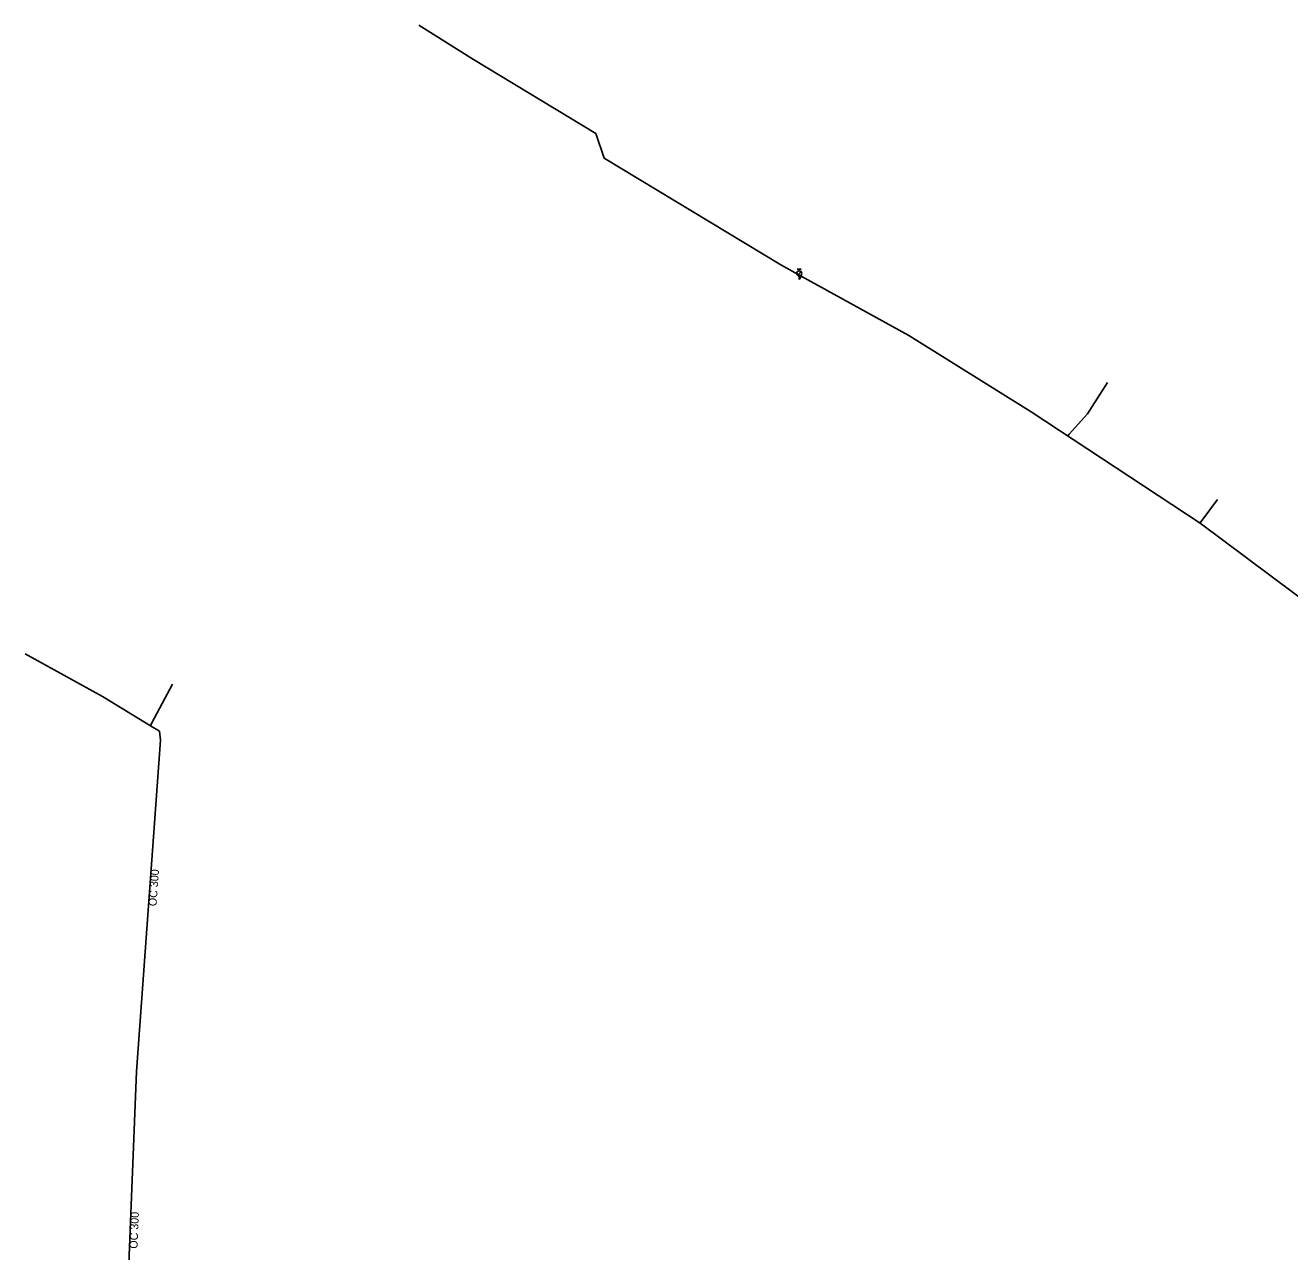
# Model space of a CAD drawing. Extents: x -513141 to -512601, y -1130827 to -1130115.
# Drawn here: x -513094.7 to -512940.6, y -1130264 to -1130114.6 of the extents above; entities that cross this region are included whole.
import ezdxf

# ---------------------------------------------------------------- set-up
doc = ezdxf.new("R2010")
doc.units = 0
for name, color, linetype in [('Default', 7, 'Continuous'), ('MoLevel 10', 7, 'Continuous'), ('MoLevel 12', 7, 'Continuous'), ('MoLevel 15', 7, 'Continuous'), ('MoLevel 32', 7, 'Continuous')]:
    doc.layers.add(name, color=color, linetype=linetype)

# ---------------------------------------------------------------- blocks, each defined once
blk = doc.blocks.new('0.05')
at = {"layer": 'Default'}
for p, q in [((-0.01, 0.05), (0.01, 0.05)), ((-0.009, 0.021), (0.009, 0.039)), ((0, 0.0425), (0, 0.05)), ((0, 0), (0, 0.0175))]:
    blk.add_line(p, q, dxfattribs=at)
blk.add_circle((0, 0.03), 0.0125, dxfattribs=at)

msp = doc.modelspace()

# ---------------------------------------------------------------- linework, layer by layer
at = {"layer": 'MoLevel 10'}
for p, q in [((-513040.02, -1130118.75), (-513046.69, -1130114.57)), ((-513025.13, -1130127.76), (-513040.02, -1130118.75)), ((-513024.13, -1130130.75), (-513025.13, -1130127.76)), ((-513002.59, -1130143.74), (-513024.13, -1130130.75)), ((-513000.09, -1130145.12), (-513002.59, -1130143.74)), ((-513000.18, -1130145.28), (-513000.34, -1130145.55)), ((-513000.09, -1130145.12), (-513000.18, -1130145.28)), ((-512986.97, -1130152.37), (-513000.09, -1130145.12)), ((-512972.06, -1130161.66), (-512986.97, -1130152.37)), ((-512951.49, -1130175.24), (-512972.06, -1130161.66)), ((-512931.11, -1130190.44), (-512951.49, -1130175.24)), ((-513094.66, -1130191.16), (-513085.27, -1130196.35)), ((-513079.22, -1130199.54), (-513076.71, -1130194.83)), ((-513085.27, -1130196.35), (-513085.06, -1130196.47)), ((-513085.06, -1130196.47), (-513079.42, -1130199.91)), ((-513079.42, -1130199.91), (-513079.22, -1130199.54)), ((-513079.42, -1130199.91), (-513078.31, -1130200.59)), ((-513078.31, -1130200.59), (-513078.19, -1130201.68)), ((-513078.19, -1130201.68), (-513081.11, -1130242.02)), ((-513081.11, -1130242.02), (-513082.81, -1130285.18))]:
    msp.add_line(p, q, dxfattribs=at)
at = {"layer": 'MoLevel 15'}
for p, q in [((-512964.92, -1130161.46), (-512962.77, -1130158.09)), ((-512967.46, -1130164.38), (-512965.2, -1130161.92)), ((-512965.2, -1130161.92), (-512964.92, -1130161.46)), ((-512967.61, -1130164.6), (-512967.46, -1130164.38)), ((-512951.36, -1130175.03), (-512949.38, -1130172.36)), ((-512951.5, -1130175.23), (-512951.36, -1130175.03))]:
    msp.add_line(p, q, dxfattribs=at)

# ---------------------------------------------------------------- block references
at = {"layer": 'MoLevel 12', "xscale": 25, "yscale": 25}
msp.add_blockref('0.05', (-513000.34, -1130145.55), dxfattribs=at)

# ---------------------------------------------------------------- texts
at = {"layer": 'MoLevel 32'}
for rotation, p in [(85.8643, (-513078.68, -1130221.92)), (87.7444, (-513080.99, -1130263.64))]:
    msp.add_text('OC 300', height=0.975, rotation=rotation, dxfattribs=at).set_placement(p)

doc.saveas('drawing.dxf')
